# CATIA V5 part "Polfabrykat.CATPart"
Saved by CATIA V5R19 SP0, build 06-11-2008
Part number: Polfabrykat
Bounding box of the stored display mesh (mm): x -44.933 to 45, y -44.968 to 44.968, z -79.746 to 38.254
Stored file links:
  G:\Catia\CD\Ustawienia\Ustawienia\Polfabrykat.CATPart
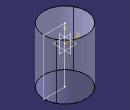
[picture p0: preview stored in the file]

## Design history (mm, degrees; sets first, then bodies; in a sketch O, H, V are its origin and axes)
Body1 "Polfabrykat" (main body)
  Sketch1 on zx-plane, origin (0, 0, 0), H (-1, 0, 0), V (0, 0, 1)
    point P1 (0, 38.2543)
    line L1 (0, 38.2543) -> (-45, 38.2543)
    line L2 (-45, 38.2543) -> (-45, -79.7457)
    line L3 (-45, -79.7457) -> (0, -79.7457)
    line L4 (0, -79.7457) -> (0, 38.2543)
    length L1 = 45
    length L2 = 118
    coincidence: P1 V
    horizontal: L1 H, L3 H
    vertical: L2 V, L4 V
  Shaft1: profile Sketch1, axis Sketch1.L4, angle 360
